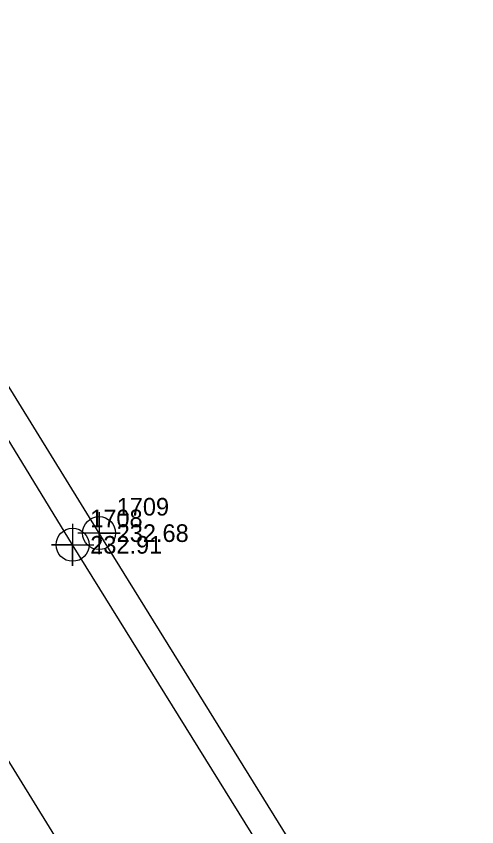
# Model space of a CAD drawing. Extents: x 2130962 to 2131465, y 643052 to 644206.
# Drawn here: x 2131204.4 to 2131269.8, y 643894.5 to 644009.5 of the extents above; entities that cross this region are included whole.
import ezdxf

# ---------------------------------------------------------------- set-up
doc = ezdxf.new("R2010")
doc.units = 0
for name, color, linetype in [('Exist Roads EOP', 7, 'Continuous'), ('Exist Roads EOP Other Cogo Elevation', 7, 'Continuous'), ('Exist Roads EOP Other Cogo Number', 7, 'Continuous'), ('Exist Roads EOP Other Cogo Point CELL', 7, 'Continuous'), ('Exist Roads EOT', 7, 'Continuous'), ('Exist Roads EOT Cogo Elevation', 7, 'Continuous'), ('Exist Roads EOT Cogo Number', 7, 'Continuous'), ('Exist Roads EOT Cogo Point CELL', 7, 'Continuous')]:
    doc.layers.add(name, color=color, linetype=linetype)

msp = doc.modelspace()

# ---------------------------------------------------------------- linework, layer by layer
at = {"layer": 'Exist Roads EOP'}
msp.add_lwpolyline([(2131269.8281, 643849.5438), (2131245.2333, 643889.3452), (2131216.1751, 643936.1301), (2131188.6585, 643980.6301), (2131160.5575, 644026.0233), (2131133.7706, 644069.3844), (2131106.5621, 644113.2921), (2131078.4587, 644158.6941), (2131052.1516, 644201.1049)], dxfattribs=at)
msp.add_spline([(2131166.2495, 643216.6951), (2131171.8131, 643218.7244), (2131182.3713, 643223.9726), (2131191.8117, 643231.1489), (2131200.5013, 643239.6993), (2131208.8071, 643249.0697), (2131216.0672, 643259.0032), (2131218.7188, 643264.347), (2131220.5363, 643270.0958), (2131222.8445, 643282.0077), (2131224.3583, 643293.9245), (2131224.8763, 643317.7904), (2131222.0632, 643367.6716), (2131218.5448, 643416.8114), (2131214.3187, 643466.3462), (2131209.1735, 643515.6666), (2131202.7939, 643565.1545), (2131195.0475, 643613.9937), (2131186.4014, 643662.4763), (2131176.0113, 643711.405), (2131164.6154, 643759.8896), (2131151.874, 643807.8526), (2131137.8554, 643855.4065), (2131122.5733, 643902.8574), (2131105.9622, 643949.4862), (2131091.5349, 643988.0437)], degree=3, dxfattribs=at)
at = {"layer": 'Exist Roads EOP Other Cogo Point CELL'}
msp.add_lwpolyline([(2131216.1751, 643939.1301), (2131216.1751, 643933.1301), (2131216.1751, 643936.1301), (2131219.1751, 643936.1301), (2131213.1751, 643936.1301)], dxfattribs=at)
msp.add_circle((2131216.1751, 643936.1301), 2.344, dxfattribs=at)
at = {"layer": 'Exist Roads EOT'}
for points in [[(2131266.2139, 643847.7337), (2131241.6557, 643887.3896), (2131212.415, 643934.4728), (2131185.0265, 643979.1763), (2131157.0131, 644024.017), (2131130.1473, 644067.7247), (2131102.8992, 644111.8313), (2131074.9921, 644156.7275), (2131048.5158, 644199.6357)], [(2131027.1782, 644188.3908), (2131054.4288, 644144.4752), (2131080.5567, 644102.0812), (2131108.007, 644057.7457), (2131134.6373, 644014.7205), (2131162.4421, 643969.638), (2131189.8746, 643925.4695), (2131217.6277, 643880.5724), (2131241.9317, 643841.1922)]]:
    msp.add_lwpolyline(points, dxfattribs=at)
msp.add_spline([(2131166.718, 643215.2083), (2131172.3866, 643217.1804), (2131211.4056, 643247.1499), (2131223.758, 643268.7314), (2131228.3848, 643317.935), (2131225.533, 643367.8628), (2131222.2486, 643417.1873), (2131217.9619, 643466.6275), (2131212.8794, 643516.2377), (2131206.5633, 643565.5764), (2131198.9021, 643614.6757), (2131189.6851, 643663.4055), (2131179.3985, 643712.1311), (2131168.3085, 643760.7185), (2131155.755, 643808.9129), (2131141.6748, 643856.5528), (2131126.5354, 643904.2758), (2131110.3559, 643951.0191), (2131092.4533, 643998.1348), (2131073.722, 644043.631), (2131053.1654, 644089.359), (2131032.0052, 644134.0908), (2131009.0644, 644179.3802)], degree=3, dxfattribs=at)
at = {"layer": 'Exist Roads EOT Cogo Point CELL'}
msp.add_lwpolyline([(2131212.415, 643937.4728), (2131212.415, 643931.4728), (2131212.415, 643934.4728), (2131209.415, 643934.4728), (2131215.415, 643934.4728)], dxfattribs=at)
msp.add_circle((2131212.415, 643934.4728), 2.344, dxfattribs=at)

# ---------------------------------------------------------------- texts
at = {"layer": 'Exist Roads EOP Other Cogo Elevation'}
msp.add_text('232.68', height=2.5, dxfattribs=at).set_placement((2131218.6751, 643934.8801))
at = {"layer": 'Exist Roads EOP Other Cogo Number'}
msp.add_text('1709', height=2.5, dxfattribs=at).set_placement((2131218.6751, 643938.6301))
at = {"layer": 'Exist Roads EOT Cogo Elevation'}
msp.add_text('232.91', height=2.5, dxfattribs=at).set_placement((2131214.915, 643933.2228))
at = {"layer": 'Exist Roads EOT Cogo Number'}
msp.add_text('1708', height=2.5, dxfattribs=at).set_placement((2131214.915, 643936.9728))

doc.saveas('drawing.dxf')
